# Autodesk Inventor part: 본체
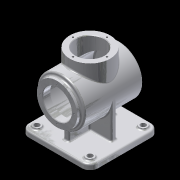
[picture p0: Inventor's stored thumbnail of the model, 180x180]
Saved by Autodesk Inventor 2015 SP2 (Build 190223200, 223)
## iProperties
Created: 2015-07
Part Number: 본체
Material: 알루미늄 6061
Document SubType Name: Modeling
Designer: AMC
Density: 2.7 g/cm^3
Appearance: 알루미늄 - 평지
Mass: 1272.91 g
Surface Area: 1267.64 cm^2
Volume: 471.446 cm^3
Author: AMC
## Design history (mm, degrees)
sketch "스케치1"
  geometry: L1 (65, -65)-(-65, -65); L2 (-65, -65)-(-65, 65); L3 (-65, 65)-(65, 65); L4 (65, 65)-(65, -65); L5 (65, -65)-(-65, 65); L6 (-65, -65)-(65, 65); 1 further point
  constraints: 12 end point, 2 midpoint, 2 parallel, 2 perpendicular, 1 horizontal
  dimensions: "d0" = 130 distance of L1.end L2.end
extrude "돌출1" new body sketch "스케치1" distance "d1" = 10; taper "d2" = 0 deg
sketch "스케치2"
  geometry: C1 r 45 at (0, 78); 1 further point
  constraints: 1 centre point, 1 vertical alignment
  dimensions: "d3" = 78 distance of point (0, 0) C1.centre; "d4" = 90 diameter of C1
extrude "돌출2" join sketch "스케치2" stored distance "d5" = 110; taper "d6" = 0 deg
sketch "스케치3"
  geometry: C1 r 45 at (0, 0) reference; C2 r 38 at (0, 0); 1 further point
  constraints: 1 centre point, 1 coincident
  dimensions: "d7" = 76 diameter of C2
extrude "돌출3" join sketch "스케치3" distance "d8" = 7; taper "d9" = 0 deg
node "작업 평면1"
sketch "스케치4"
  geometry: C1 r 38 at (0, 0); 1 further point
  constraints: 1 centre point, 1 coincident
  dimensions: "d11" = 76 diameter of C1
extrude "돌출4" join sketch "스케치4" stored distance "d12" = 7; taper "d13" = 0 deg
sketch "스케치5"
  geometry: L1 (-62, 116)-(-62, 40) reference; L2 (55, 33)-(55, 123) reference; L3 (-62, 78)-(55, 78); L4 (-62, 105)-(-48, 105); L5 (-48, 105)-(-48, 115); L6 (-45, 118)-(45, 118); L7 (48, 115)-(48, 78); A1 r 3 centre (-45, 115) between (-45, 118) and (-48, 115); A2 r 3 centre (45, 115) between (48, 115) and (45, 118); 1 further point
  constraints: 10 end point, 4 point on circle, 4 tangent, 3 perpendicular, 2 centre point, 2 midpoint, 2 point on line, 1 horizontal
  dimensions: "d14" = 14 distance between parallel lines of L5 L1; "d15" = 96 distance between parallel lines of L7 L5; "d16" = 54 diameter of L4 L3; "d17" = 80 diameter of L6 L3; "d18" = 3 radius of A1; "d19" = 3 radius of A2
revolve "회전1" sketch "스케치5" stored, may be unused: angle "d20" = 90 deg
hole "구멍1" diameter "d23" = 54; stored, may be unused: countersink angle "d27" = 90 deg, drill point angle "d29" = 118 deg; dims "d21" = 10, "d22" = 10, "d24" = 6, "d25" = 54, "d26" = 14, "d28" = 8
sketch "스케치6"
  geometry: 2 further points
  constraints: 1 horizontal alignment
  dimensions: "d30" = 32 distance of point (0, 0) point (-32, 0)
hole "구멍2" sketch "스케치6" at (-32, 0) diameter "d31" = 3.242; stored, may be unused: countersink angle "d35" = 90 deg, drill point angle "d37" = 118 deg; dims "d32" = 8, "d33" = 54, "d34" = 14, "d36" = 10
sketch "스케치7"
  geometry: C1 r 27 at (0, 0) reference; 2 further points
  constraints: 1 vertical alignment
  dimensions: "d41" = 32 distance of C1.centre point (0, 32)
hole "구멍3" sketch "스케치7" at (0, 32) diameter "d42" = 3.242; stored, may be unused: countersink angle "d46" = 90 deg, drill point angle "d48" = 118 deg; dims "d43" = 8, "d44" = 54, "d45" = 14, "d47" = 10
sketch "스케치8"
  geometry: L1 (65, 0)-(-65, 0) reference; L2 (65, 0)-(65, 10) reference; L3 (-65, 10)-(65, 10) reference; L4 (-65, 0)-(-65, 10) reference; L5 (45, 78)-(45, 10); L6 (-65, 10)-(65, 10) reference; L7 (-45, 78)-(-45, 10); A1 r 45 centre (0, 78) between (45, 78) and (-45, 78) reference; 1 further point
  constraints: 4 end point, 2 point on circle, 2 point on line, 2 tangent, 1 parallel, 1 perpendicular, 1 vertical
extrude "돌출5" join sketch "스케치8" stored distance "d52" = 10; taper "d53" = 0 deg
sketch "스케치9"
  geometry: L1 (-55, 33)-(55, 33) reference; L2 (65, 10)-(-65, 10) reference; L3 (-45, 10)-(-45, 33); 1 further point
  constraints: 2 end point, 2 point on line, 1 perpendicular
  dimensions: "d54" = 45 distance from line of point (0, 0) L3
feature "리브1" sketch "스케치9" dims "d55" = 1, "d56" = 10, "d57" = 0, "d58" = 0, "d59" = 1, "d60" = 1
fillet "모깎기1" dims "d61" = 15
sketch "스케치10"
  geometry: C1 r 7.5 at (50, -50); 1 further point
  constraints: 1 centre point
  dimensions: "d62" = 15 diameter of C1; "d63" = 50 horizontal distance of point (0, 0) C1.centre; "d64" = 50 horizontal distance of point (0, 0) C1.centre
extrude "돌출6" join sketch "스케치10" distance "d65" = 3; taper "d66" = 0 deg
sketch "스케치11"
  geometry: C1 r 7.5 at (0, 0) reference; C2 r 5 at (0, 0); 1 further point
  constraints: 1 centre point, 1 coincident
  dimensions: "d67" = 10 diameter of C2
extrude "돌출7" cut sketch "스케치11" stored distance "d68" = 3; taper "d69" = 0 deg
fillet "모깎기2" dims "d70" = 3
fillet "모깎기3" dims "d77" = 3
fillet "모깎기4" dims "d78" = 3
chamfer "모따기1" distance "d79" = 1; stored, may be unused: second distance "d80" = 2, angle "d81" = 45 deg
sketch "스케치12"
  geometry: C1 r 42 at (0, 0) reference; 2 further points
  constraints: 2 coincident, 1 other
feature "엠보싱1" sketch "스케치12" dims "d0" = 130, "d11" = 76, "d82" = 0.5, "d83" = 0
node "솔리드1"
pattern_circular "원형 패턴1" dims angle "d39" = 360 deg
pattern_circular "원형 패턴2" dims angle "d50" = 360 deg
mirror "대칭1"
pattern_linear "직사각형 패턴1"
node "투영된 루프1"
node "투영된 루프2"
node "투영된 루프3"
